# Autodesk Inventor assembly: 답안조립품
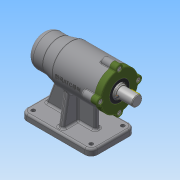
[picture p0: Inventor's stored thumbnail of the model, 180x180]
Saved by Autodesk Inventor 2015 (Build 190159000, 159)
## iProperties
Created: 2019-07
Part Number: 답안조립품
Document SubType Name: Assembly
Designer: user
Author: user
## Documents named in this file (12)
- C:\Users\user\Desktop\490704V1054\답안조립품.iam
- C:\Users\user\Desktop\490704V1054\답안도면.ipt
- C:\Users\user\Desktop\490704V1054\커버.ipt
- C:\Users\user\Desktop\490704V1054\축.ipt
- C:\Users\user\Desktop\490704V1054\베어링 6004.ipt
- C:\Users\user\Desktop\490704V1054\어댑터슬리브.ipt
- C:\Users\user\Desktop\490704V1054\베어링 51202.ipt
- C:\Users\user\Desktop\490704V1054\오일 실.ipt
- C:\Users\user\Desktop\490704V1054\키 5 x 5 x 16.ipt
- C:\Users\user\Desktop\490704V1054\V벨트풀리.ipt
- C:\Users\user\Desktop\490704V1054\멈춤나사 M3.ipt
- C:\Users\user\Desktop\490704V1054\볼트 M4.ipt
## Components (1 placed, 1 different names)
1. V벨트풀리:1 — 각도:1
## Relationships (1: Angle 1)
- 각도:1 [Angle]: V벨트풀리:1
